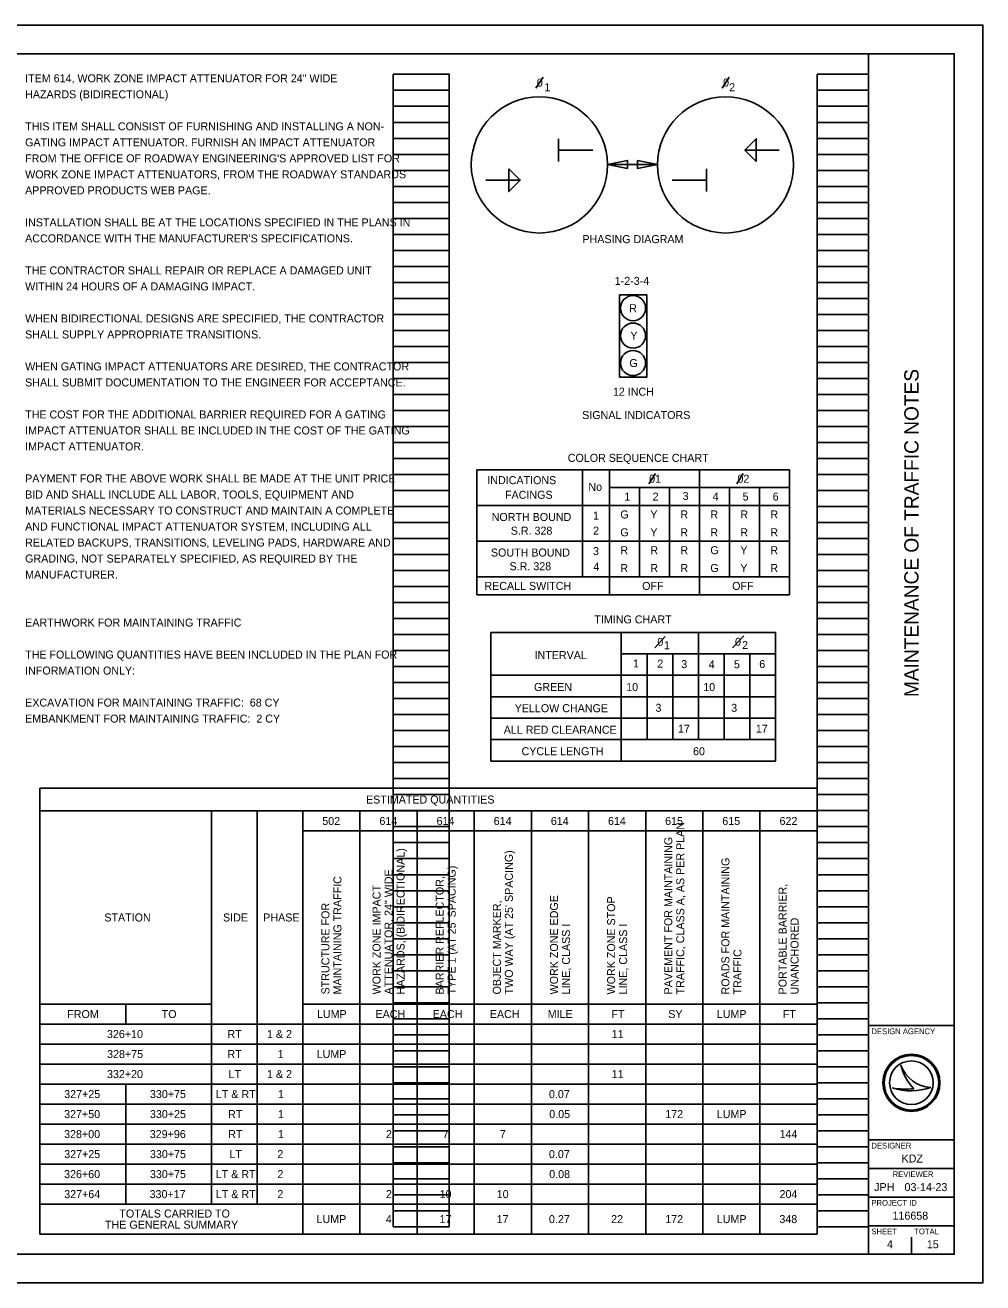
# Model space of a CAD drawing. Extents: x 0 to 74, y -29.1 to 22.
# Drawn here: x 17.24 to 34, y 0 to 22 of the extents above; entities that cross this region are included whole.
import ezdxf

# ---------------------------------------------------------------- set-up
doc = ezdxf.new("R2010")
doc.units = 0
for name, color, linetype in [('Default', 7, 'Continuous'), ('SG_P_Heads', 7, 'Continuous'), ('SH_Border', 7, 'Continuous'), ('SH_Cut_Line', 7, 'Continuous'), ('SH_Data', 7, 'Continuous'), ('SH_Text', 7, 'Continuous'), ('TX_P_1', 7, 'Continuous')]:
    doc.layers.add(name, color=color, linetype=linetype)

msp = doc.modelspace()

# ---------------------------------------------------------------- linework, layer by layer
at = {"layer": 'Default'}
for p, q in [((28.119, 17.285), (27.641, 17.285)), ((27.641, 17.285), (27.641, 15.844)), ((28.119, 15.844), (28.119, 17.285)), ((27.641, 15.844), (28.119, 15.844)), ((25.145, 14.223), (25.145, 12.036)), ((25.145, 14.223), (30.615, 14.223)), ((26.996, 14.223), (26.996, 12.348)), ((27.465, 14.223), (27.465, 12.036)), ((29.04, 14.223), (29.04, 12.036)), ((30.615, 14.223), (30.615, 12.036)), ((30.615, 14.223), (30.615, 12.036)), ((27.465, 13.911), (30.615, 13.911)), ((27.99, 13.911), (27.99, 12.348)), ((28.515, 13.911), (28.515, 12.348)), ((29.565, 13.911), (29.565, 12.348)), ((30.09, 13.911), (30.09, 12.348)), ((25.145, 13.598), (30.615, 13.598)), ((25.145, 12.973), (30.615, 12.973)), ((25.145, 12.348), (30.615, 12.348)), ((25.145, 12.036), (30.615, 12.036)), ((25.387, 11.377), (30.373, 11.377)), ((25.387, 11.377), (25.387, 9.127)), ((27.673, 11.377), (27.673, 9.127)), ((29.023, 11.377), (29.023, 9.502)), ((30.373, 11.377), (30.373, 9.127)), ((27.673, 11.002), (30.373, 11.002)), ((28.123, 11.002), (28.123, 9.502)), ((28.573, 11.002), (28.573, 9.502)), ((29.473, 11.002), (29.473, 9.502)), ((29.923, 11.002), (29.923, 9.502)), ((25.387, 10.627), (30.373, 10.627)), ((25.387, 10.252), (30.373, 10.252)), ((25.387, 9.877), (30.373, 9.877)), ((25.387, 9.502), (30.373, 9.502)), ((25.387, 9.127), (30.373, 9.127))]:
    msp.add_line(p, q, dxfattribs=at)
for centre in [(27.879, 17.049), (27.879, 16.569), (27.879, 16.09)]:
    msp.add_circle(centre, 0.22, dxfattribs=at)
at = {"layer": 'SG_P_Heads'}
for p, q in [((26.574, 20.014), (26.574, 19.614)), ((27.175, 19.814), (26.574, 19.814)), ((30.434, 19.814), (29.834, 19.814)), ((29.164, 19.089), (29.164, 19.489)), ((25.304, 19.289), (25.905, 19.289)), ((28.563, 19.289), (29.164, 19.289))]:
    msp.add_line(p, q, dxfattribs=at)
for points in [[(30.034, 19.614), (29.834, 19.814), (30.034, 20.014)], [(27.782, 19.493), (27.432, 19.563), (27.782, 19.633)], [(27.955, 19.633), (28.305, 19.563), (27.955, 19.493)], [(25.705, 19.489), (25.905, 19.289), (25.705, 19.089)]]:
    msp.add_lwpolyline(points, close=True, dxfattribs=at)
at = {"layer": 'SH_Border'}
for p, q in [((32, 0.5), (32, 21.5)), ((32, 4.5), (33.5, 4.5)), ((32, 2.5), (33.5, 2.5)), ((32, 2), (33.5, 2)), ((32, 1.5), (33.5, 1.5)), ((32, 1), (33.5, 1))]:
    msp.add_line(p, q, dxfattribs=at)
msp.add_lwpolyline([(1.5, 21.5), (33.5, 21.5), (33.5, 0.5), (1.5, 0.5)], close=True, dxfattribs=at)
at = {"layer": 'SH_Cut_Line'}
msp.add_lwpolyline([(0, 0), (34, 0), (34, 22), (0, 22)], close=True, dxfattribs=at)
at = {"layer": 'SH_Data'}
for p, q in [((23.68, 0.98), (23.68, 21.14)), ((23.68, 21.14), (24.66, 21.14)), ((24.66, 0.98), (24.66, 21.14)), ((31.1, 0.98), (31.1, 21.14)), ((31.1, 21.14), (32, 21.14)), ((32, 0.98), (32, 21.14)), ((23.68, 20.86), (24.66, 20.86)), ((31.1, 20.86), (32, 20.86)), ((23.68, 20.58), (24.66, 20.58)), ((31.1, 20.58), (32, 20.58)), ((23.68, 20.3), (24.66, 20.3)), ((31.1, 20.3), (32, 20.3)), ((23.68, 20.02), (24.66, 20.02)), ((31.1, 20.02), (32, 20.02)), ((23.68, 19.74), (24.66, 19.74)), ((31.1, 19.74), (32, 19.74)), ((23.68, 19.46), (24.66, 19.46)), ((28.305, 19.563), (27.432, 19.563)), ((31.1, 19.46), (32, 19.46)), ((23.68, 19.18), (24.66, 19.18)), ((31.1, 19.18), (32, 19.18)), ((23.68, 18.9), (24.66, 18.9)), ((31.1, 18.9), (32, 18.9)), ((23.68, 18.62), (24.66, 18.62)), ((31.1, 18.62), (32, 18.62)), ((23.68, 18.34), (24.66, 18.34)), ((31.1, 18.34), (32, 18.34)), ((23.68, 18.06), (24.66, 18.06)), ((31.1, 18.06), (32, 18.06)), ((23.68, 17.78), (24.66, 17.78)), ((31.1, 17.78), (32, 17.78)), ((23.68, 17.5), (24.66, 17.5)), ((31.1, 17.5), (32, 17.5)), ((23.68, 17.22), (24.66, 17.22)), ((31.1, 17.22), (32, 17.22)), ((23.68, 16.94), (24.66, 16.94)), ((31.1, 16.94), (32, 16.94)), ((23.68, 16.66), (24.66, 16.66)), ((31.1, 16.66), (32, 16.66)), ((23.68, 16.38), (24.66, 16.38)), ((31.1, 16.38), (32, 16.38)), ((23.68, 16.1), (24.66, 16.1)), ((31.1, 16.1), (32, 16.1)), ((23.68, 15.82), (24.66, 15.82)), ((31.1, 15.82), (32, 15.82)), ((23.68, 15.54), (24.66, 15.54)), ((31.1, 15.54), (32, 15.54)), ((23.68, 15.26), (24.66, 15.26)), ((31.1, 15.26), (32, 15.26)), ((23.68, 14.98), (24.66, 14.98)), ((31.1, 14.98), (32, 14.98)), ((23.68, 14.7), (24.66, 14.7)), ((31.1, 14.7), (32, 14.7)), ((23.68, 14.42), (24.66, 14.42)), ((31.1, 14.42), (32, 14.42)), ((23.68, 14.14), (24.66, 14.14)), ((31.1, 14.14), (32, 14.14)), ((23.68, 13.86), (24.66, 13.86)), ((31.1, 13.86), (32, 13.86)), ((23.68, 13.58), (24.66, 13.58)), ((31.1, 13.58), (32, 13.58)), ((23.68, 13.3), (24.66, 13.3)), ((31.1, 13.3), (32, 13.3)), ((23.68, 13.02), (24.66, 13.02)), ((31.1, 13.02), (32, 13.02)), ((23.68, 12.74), (24.66, 12.74)), ((31.1, 12.74), (32, 12.74)), ((23.68, 12.46), (24.66, 12.46)), ((31.1, 12.46), (32, 12.46)), ((23.68, 12.18), (24.66, 12.18)), ((31.1, 12.18), (32, 12.18)), ((23.68, 11.9), (24.66, 11.9)), ((31.1, 11.9), (32, 11.9)), ((23.68, 11.62), (24.66, 11.62)), ((31.1, 11.62), (32, 11.62)), ((23.68, 11.34), (24.66, 11.34)), ((31.1, 11.34), (32, 11.34)), ((23.68, 11.06), (24.66, 11.06)), ((31.1, 11.06), (32, 11.06)), ((23.68, 10.78), (24.66, 10.78)), ((31.1, 10.78), (32, 10.78)), ((23.68, 10.5), (24.66, 10.5)), ((31.1, 10.5), (32, 10.5)), ((23.68, 10.22), (24.66, 10.22)), ((31.1, 10.22), (32, 10.22)), ((23.68, 9.94), (24.66, 9.94)), ((31.1, 9.94), (32, 9.94)), ((23.68, 9.66), (24.66, 9.66)), ((31.1, 9.66), (32, 9.66)), ((23.68, 9.38), (24.66, 9.38)), ((31.1, 9.38), (32, 9.38)), ((23.68, 9.1), (24.66, 9.1)), ((31.1, 9.1), (32, 9.1)), ((23.68, 8.82), (24.66, 8.82)), ((31.1, 8.82), (32, 8.82)), ((23.68, 8.54), (24.66, 8.54)), ((31.1, 8.54), (32, 8.54)), ((23.68, 8.26), (24.66, 8.26)), ((31.1, 8.26), (32, 8.26)), ((23.68, 7.98), (24.66, 7.98)), ((31.1, 7.98), (32, 7.98)), ((23.68, 7.7), (24.66, 7.7)), ((31.1, 7.7), (32, 7.7)), ((23.68, 7.42), (24.66, 7.42)), ((31.1, 7.42), (32, 7.42)), ((23.68, 7.14), (24.66, 7.14)), ((31.1, 7.14), (32, 7.14)), ((23.68, 6.86), (24.66, 6.86)), ((31.1, 6.86), (32, 6.86)), ((23.68, 6.58), (24.66, 6.58)), ((31.1, 6.58), (32, 6.58)), ((23.68, 6.3), (24.66, 6.3)), ((31.1, 6.3), (32, 6.3)), ((23.68, 6.02), (24.66, 6.02)), ((31.1, 6.02), (32, 6.02)), ((23.68, 5.74), (24.66, 5.74)), ((31.1, 5.74), (32, 5.74)), ((23.68, 5.46), (24.66, 5.46)), ((31.1, 5.46), (32, 5.46)), ((23.68, 5.18), (24.66, 5.18)), ((31.1, 5.18), (32, 5.18)), ((23.68, 4.9), (24.66, 4.9)), ((31.1, 4.9), (32, 4.9)), ((23.68, 4.62), (24.66, 4.62)), ((31.1, 4.62), (32, 4.62)), ((23.68, 4.34), (24.66, 4.34)), ((31.1, 4.34), (32, 4.34)), ((23.68, 4.06), (24.66, 4.06)), ((31.1, 4.06), (32, 4.06)), ((23.68, 3.78), (24.66, 3.78)), ((31.1, 3.78), (32, 3.78)), ((32.567, 3.81), (32.567, 3.81)), ((23.68, 3.5), (24.66, 3.5)), ((31.1, 3.5), (32, 3.5)), ((32.417, 3.41), (32.417, 3.41)), ((32.75, 3.5), (32.75, 3.5)), ((33.087, 3.419), (33.087, 3.419)), ((23.68, 3.22), (24.66, 3.22)), ((31.1, 3.22), (32, 3.22)), ((23.68, 2.94), (24.66, 2.94)), ((31.1, 2.94), (32, 2.94)), ((23.68, 2.66), (24.66, 2.66)), ((31.1, 2.66), (32, 2.66)), ((23.68, 2.38), (24.66, 2.38)), ((31.1, 2.38), (32, 2.38)), ((23.68, 2.1), (24.66, 2.1)), ((31.1, 2.1), (32, 2.1)), ((23.68, 1.82), (24.66, 1.82)), ((31.1, 1.82), (32, 1.82)), ((23.68, 1.54), (24.66, 1.54)), ((31.1, 1.54), (32, 1.54)), ((23.68, 1.26), (24.66, 1.26)), ((31.1, 1.26), (32, 1.26)), ((23.68, 0.98), (24.66, 0.98)), ((31.1, 0.98), (32, 0.98)), ((32.375, 0.675), (32.375, 0.675)), ((32.75, 0.5), (32.75, 0.8))]:
    msp.add_line(p, q, dxfattribs=at)
for centre, radius in [((26.239, 19.555), 1.191), ((29.498, 19.555), 1.191), ((32.75, 3.5), 0.5), ((32.75, 3.5), 0.477), ((32.75, 3.5), 0.477), ((32.75, 3.5), 0.382)]:
    msp.add_circle(centre, radius, dxfattribs=at)
for centre, radius, start, end in [((33.116, 3.998), 0.58, 198.9257, 198.9319), ((33.347, 3.97), 0.796, 191.6379, 191.6421), ((33.116, 3.998), 0.58, 198.9319, 267.1657), ((33.347, 3.97), 0.796, 191.6421, 226.0947), ((32.739, 4.37), 1.013, 251.4576, 290.0832), ((32.648, 4.654), 1.266, 259.4964, 259.4995), ((32.739, 4.37), 1.013, 251.4527, 251.4576), ((32.648, 4.654), 1.266, 259.4995, 276.6672)]:
    msp.add_arc(centre, radius, start, end, dxfattribs=at)
at = {"layer": 'SH_Text'}
for p, q in [((17.5, 0.852), (17.5, 8.654)), ((17.5, 8.654), (31.1, 8.654)), ((31.1, 0.852), (31.1, 8.654)), ((17.5, 8.254), (31.1, 8.254)), ((20.5, 1.377), (20.5, 8.254)), ((21.3, 1.377), (21.3, 8.254)), ((22.1, 0.852), (22.1, 8.254)), ((23.1, 0.852), (23.1, 8.254)), ((24.1, 0.852), (24.1, 8.254)), ((25.1, 0.852), (25.1, 8.254)), ((26.1, 0.852), (26.1, 8.254)), ((27.1, 0.852), (27.1, 8.254)), ((28.1, 0.852), (28.1, 8.254)), ((29.1, 0.852), (29.1, 8.254)), ((30.1, 0.852), (30.1, 8.254)), ((22.1, 7.904), (31.1, 7.904)), ((17.5, 4.877), (20.5, 4.877)), ((19, 4.527), (19, 4.877)), ((22.1, 4.877), (31.1, 4.877)), ((17.5, 4.527), (31.1, 4.527)), ((17.5, 4.177), (31.1, 4.177)), ((17.5, 3.827), (31.1, 3.827)), ((17.5, 3.477), (31.1, 3.477)), ((19, 1.377), (19, 3.477)), ((17.5, 3.127), (31.1, 3.127)), ((17.5, 2.777), (31.1, 2.777)), ((17.5, 2.427), (31.1, 2.427)), ((17.5, 2.077), (31.1, 2.077)), ((17.5, 1.727), (31.1, 1.727)), ((17.5, 1.377), (31.1, 1.377)), ((17.5, 0.852), (31.1, 0.852))]:
    msp.add_line(p, q, dxfattribs=at)
at = {"layer": 'TX_P_1'}
for p, q in [((26.303, 21.088), (26.178, 20.895)), ((29.563, 21.088), (29.437, 20.895)), ((28.155, 13.976), (28.27, 14.157)), ((29.693, 13.976), (29.808, 14.157)), ((28.262, 11.107), (28.439, 11.308)), ((29.619, 11.109), (29.819, 11.318))]:
    msp.add_line(p, q, dxfattribs=at)

# ---------------------------------------------------------------- texts
at = {"layer": 'Default'}
for s, p in [('R', (27.811, 16.979)), ('Y', (27.831, 16.499)), ('G', (27.815, 16.02)), ('SIGNAL INDICATORS', (26.988, 15.11)), ('COLOR SEQUENCE CHART', (26.736, 14.361)), ('TIMING CHART', (27.202, 11.535))]:
    msp.add_text(s, height=0.14, dxfattribs=at).set_placement(p)
at = {"layer": 'SH_Data'}
for s, height, p in [('0', 0.14, (26.195, 20.926)), ('DESIGN AGENCY', 0.1, (32.05, 4.35)), ('DESIGNER', 0.1, (32.05, 2.35)), ('KDZ', 0.14, (32.577, 2.105)), ('REVIEWER', 0.1, (32.422, 1.85)), ('JPH', 0.14, (32.098, 1.605)), ('03-14-23', 0.14, (32.629, 1.605)), ('PROJECT ID', 0.1, (32.05, 1.35)), ('116658', 0.14, (32.419, 1.105)), ('SHEET', 0.1, (32.05, 0.85)), ('TOTAL', 0.1, (32.8, 0.85)), ('4', 0.14, (32.322, 0.605)), ('15', 0.14, (33.02, 0.605))]:
    msp.add_text(s, height=height, dxfattribs=at).set_placement(p)
msp.add_text('MAINTENANCE OF TRAFFIC NOTES', height=0.25, rotation=90, dxfattribs=at).set_placement((32.875, 10.247))
at = {"layer": 'SH_Text'}
for s, p in [('ITEM 614, WORK ZONE IMPACT ATTENUATOR FOR 24" WIDE', (17.24, 21)), ('HAZARDS (BIDIRECTIONAL)', (17.24, 20.72)), ('THIS ITEM SHALL CONSIST OF FURNISHING AND INSTALLING A NON-', (17.24, 20.16)), ('GATING IMPACT ATTENUATOR. FURNISH AN IMPACT ATTENUATOR ', (17.24, 19.88)), ("FROM THE OFFICE OF ROADWAY ENGINEERING'S APPROVED LIST FOR ", (17.24, 19.6)), ('WORK ZONE IMPACT ATTENUATORS, FROM THE ROADWAY STANDARDS ', (17.24, 19.32)), ('APPROVED PRODUCTS WEB PAGE.', (17.24, 19.04)), ('INSTALLATION SHALL BE AT THE LOCATIONS SPECIFIED IN THE PLANS IN ', (17.24, 18.48)), ("ACCORDANCE WITH THE MANUFACTURER'S SPECIFICATIONS.", (17.24, 18.2)), ('THE CONTRACTOR SHALL REPAIR OR REPLACE A DAMAGED UNIT ', (17.24, 17.64)), ('WITHIN 24 HOURS OF A DAMAGING IMPACT.', (17.24, 17.36)), ('WHEN BIDIRECTIONAL DESIGNS ARE SPECIFIED, THE CONTRACTOR ', (17.24, 16.8)), ('SHALL SUPPLY APPROPRIATE TRANSITIONS.', (17.24, 16.52)), ('WHEN GATING IMPACT ATTENUATORS ARE DESIRED, THE CONTRACTOR ', (17.24, 15.96)), ('SHALL SUBMIT DOCUMENTATION TO THE ENGINEER FOR ACCEPTANCE.', (17.24, 15.68)), ('THE COST FOR THE ADDITIONAL BARRIER REQUIRED FOR A GATING ', (17.24, 15.12)), ('IMPACT ATTENUATOR SHALL BE INCLUDED IN THE COST OF THE GATING ', (17.24, 14.84)), ('IMPACT ATTENUATOR.', (17.24, 14.56)), ('PAYMENT FOR THE ABOVE WORK SHALL BE MADE AT THE UNIT PRICE ', (17.24, 14)), ('BID AND SHALL INCLUDE ALL LABOR, TOOLS, EQUIPMENT AND ', (17.24, 13.72)), ('MATERIALS NECESSARY TO CONSTRUCT AND MAINTAIN A COMPLETE ', (17.24, 13.44)), ('AND FUNCTIONAL IMPACT ATTENUATOR SYSTEM, INCLUDING ALL ', (17.24, 13.16)), ('RELATED BACKUPS, TRANSITIONS, LEVELING PADS, HARDWARE AND ', (17.24, 12.88)), ('GRADING, NOT SEPARATELY SPECIFIED, AS REQUIRED BY THE ', (17.24, 12.6)), ('MANUFACTURER.', (17.24, 12.32)), ('EARTHWORK FOR MAINTAINING TRAFFIC', (17.24, 11.48)), ('THE FOLLOWING QUANTITIES HAVE BEEN INCLUDED IN THE PLAN FOR ', (17.24, 10.92)), ('INFORMATION ONLY:', (17.24, 10.64)), ('EXCAVATION FOR MAINTAINING TRAFFIC:  68 CY', (17.24, 10.08)), ('EMBANKMENT FOR MAINTAINING TRAFFIC:  2 CY', (17.24, 9.8)), ('ESTIMATED QUANTITIES', (23.206, 8.384)), ('502', (22.44, 8.009)), ('614', (23.44, 8.009)), ('614', (24.44, 8.009)), ('614', (25.44, 8.009)), ('614', (26.44, 8.009)), ('614', (27.44, 8.009)), ('615', (28.44, 8.009)), ('615', (29.44, 8.009)), ('622', (30.442, 8.009)), ('STATION', (18.626, 6.321)), ('SIDE', (20.703, 6.321)), ('PHASE', (21.407, 6.321)), ('FROM', (17.977, 4.632)), ('TO', (19.63, 4.632)), ('LUMP', (22.347, 4.632)), ('EACH', (23.372, 4.632)), ('EACH', (24.372, 4.632)), ('EACH', (25.372, 4.632)), ('MILE', (26.385, 4.632)), ('FT', (27.5, 4.632)), ('SY', (28.495, 4.632)), ('LUMP', (29.343, 4.632)), ('FT', (30.5, 4.632)), ('326+10', (18.672, 4.282)), ('RT', (20.781, 4.282)), ('1 & 2', (21.473, 4.282)), ('11', (27.504, 4.282)), ('328+75', (18.674, 3.932)), ('RT', (20.781, 3.932)), ('1', (21.66, 3.932)), ('LUMP', (22.342, 3.932)), ('332+20', (18.672, 3.582)), ('LT', (20.801, 3.582)), ('1 & 2', (21.473, 3.582)), ('11', (27.504, 3.582)), ('327+25', (17.924, 3.232)), ('330+75', (19.424, 3.232)), ('LT & RT', (20.578, 3.232)), ('1', (21.665, 3.232)), ('0.07', (26.407, 3.232)), ('327+50', (17.922, 2.882)), ('330+25', (19.424, 2.882)), ('RT', (20.793, 2.882)), ('1', (21.665, 2.882)), ('0.05', (26.412, 2.882)), ('172', (28.442, 2.882)), ('LUMP', (29.343, 2.882)), ('328+00', (17.922, 2.532)), ('329+96', (19.421, 2.532)), ('RT', (20.795, 2.532)), ('1', (21.665, 2.532)), ('2', (23.554, 2.532)), ('7', (24.547, 2.532)), ('7', (25.547, 2.532)), ('144', (30.442, 2.532)), ('327+25', (17.924, 2.182)), ('330+75', (19.424, 2.182)), ('LT', (20.814, 2.182)), ('2', (21.654, 2.182)), ('0.07', (26.407, 2.182)), ('326+60', (17.922, 1.832)), ('330+75', (19.424, 1.832)), ('LT & RT', (20.576, 1.832)), ('2', (21.654, 1.832)), ('0.08', (26.411, 1.832)), ('327+64', (17.924, 1.482)), ('330+17', (19.418, 1.482)), ('LT & RT', (20.578, 1.482)), ('2', (21.654, 1.482)), ('2', (23.554, 1.482)), ('10', (24.493, 1.482)), ('10', (25.493, 1.482)), ('204', (30.442, 1.482)), ('TOTALS CARRIED TO', (18.889, 1.142)), ('LUMP', (22.34, 1.045)), ('4', (23.552, 1.045)), ('17', (24.491, 1.045)), ('17', (25.491, 1.045)), ('0.27', (26.407, 1.045)), ('22', (27.495, 1.045)), ('172', (28.442, 1.045)), ('LUMP', (29.343, 1.045)), ('348', (30.439, 1.045)), ('THE GENERAL SUMMARY', (18.638, 0.947))]:
    msp.add_text(s, height=0.14, dxfattribs=at).set_placement(p)
for s, p in [('TRAFFIC, CLASS A, AS PER PLAN', (28.775, 5.045)), ('PAVEMENT FOR MAINTAINING', (28.565, 5.045)), ('HAZARDS, (BIDIRECTIONAL)', (23.88, 5.045)), ("TWO WAY (AT 25' SPACING)", (25.775, 5.045)), ("TYPE 1 (AT 25' SPACING)", (24.775, 5.045)), ('ROADS FOR MAINTAINING', (29.565, 5.045)), ('MAINTAINING TRAFFIC', (22.775, 5.045)), ('ATTENUATOR, 24" WIDE', (23.67, 5.045)), ('BARRIER REFLECTOR,', (24.565, 5.045)), ('WORK ZONE IMPACT', (23.46, 5.045)), ('PORTABLE BARRIER,', (30.565, 5.045)), ('STRUCTURE FOR ', (22.565, 5.045)), ('OBJECT MARKER,', (25.565, 5.045)), ('WORK ZONE EDGE', (26.565, 5.045)), ('WORK ZONE STOP', (27.565, 5.045)), ('LINE, CLASS I', (26.775, 5.045)), ('LINE, CLASS I', (27.775, 5.045)), ('UNANCHORED', (30.775, 5.045)), ('TRAFFIC', (29.775, 5.045))]:
    msp.add_text(s, height=0.14, rotation=90, dxfattribs=at).set_placement(p)
at = {"layer": 'TX_P_1'}
for s, p in [('1', (26.328, 20.844)), ('0', (29.454, 20.926)), ('2', (29.561, 20.844)), ('PHASING DIAGRAM', (26.992, 18.187)), ('1-2-3-4', (27.558, 17.457)), ('12 INCH', (27.526, 15.518)), ('INDICATIONS', (25.328, 13.971)), ('01', (28.16, 13.996)), ('02', (29.705, 13.996)), ('No', (27.097, 13.853)), ('FACINGS', (25.638, 13.715)), ('1', (27.727, 13.684)), ('2', (28.221, 13.684)), ('3', (28.746, 13.694)), ('4', (29.271, 13.684)), ('5', (29.796, 13.684)), ('6', (30.321, 13.684)), ('NORTH BOUND', (25.404, 13.327)), ('1', (27.178, 13.351)), ('G', (27.656, 13.371)), ('Y', (28.181, 13.371)), ('R', (28.706, 13.371)), ('R', (29.231, 13.371)), ('R', (29.756, 13.371)), ('R', (30.281, 13.371)), ('S.R. 328', (25.738, 13.087)), ('2', (27.178, 13.087)), ('G', (27.656, 13.059)), ('Y', (28.181, 13.059)), ('R', (28.706, 13.059)), ('R', (29.231, 13.059)), ('R', (29.756, 13.059)), ('R', (30.281, 13.059)), ('SOUTH BOUND', (25.391, 12.705)), ('3', (27.178, 12.73)), ('R', (27.656, 12.746)), ('R', (28.181, 12.746)), ('R', (28.706, 12.746)), ('G', (29.231, 12.746)), ('Y', (29.756, 12.746)), ('R', (30.281, 12.746)), ('S.R. 328', (25.717, 12.465)), ('4', (27.183, 12.458)), ('R', (27.656, 12.434)), ('R', (28.181, 12.434)), ('R', (28.706, 12.434)), ('G', (29.231, 12.434)), ('Y', (29.756, 12.434)), ('R', (30.281, 12.434)), ('RECALL SWITCH', (25.277, 12.121)), ('OFF', (28.038, 12.121)), ('OFF', (29.613, 12.121)), ('0', (28.304, 11.14)), ('1', (28.419, 11.084)), ('0', (29.663, 11.143)), ('2', (29.787, 11.087)), ('INTERVAL ', (26.155, 10.911)), ('1', (27.878, 10.765)), ('2', (28.302, 10.762)), ('3', (28.723, 10.753)), ('4', (29.202, 10.749)), ('5', (29.644, 10.751)), ('6', (30.087, 10.754)), (' GREEN', (26.094, 10.353)), ('10', (27.758, 10.351)), ('10', (29.107, 10.351)), ('YELLOW CHANGE', (25.807, 9.982)), ('3', (28.271, 9.989)), ('3', (29.596, 9.989)), ('ALL RED CLEARANCE', (25.616, 9.605)), ('17', (28.665, 9.624)), ('17', (30.027, 9.624)), ('CYCLE LENGTH', (25.927, 9.229)), ('60', (28.928, 9.229))]:
    msp.add_text(s, height=0.14, dxfattribs=at).set_placement(p)

doc.saveas('drawing.dxf')
